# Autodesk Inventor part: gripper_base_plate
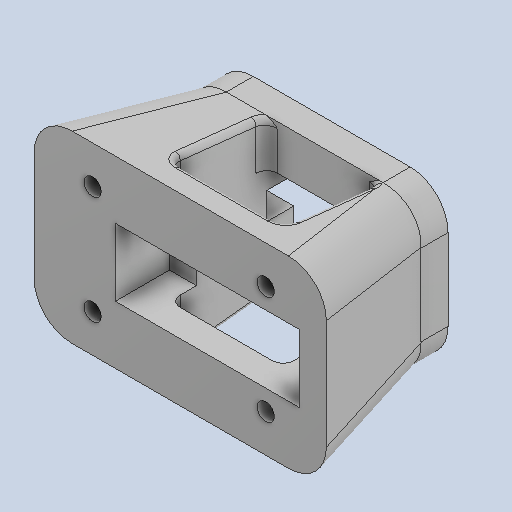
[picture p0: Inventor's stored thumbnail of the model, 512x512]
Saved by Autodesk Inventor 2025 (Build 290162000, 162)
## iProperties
Created: 2025-06
Part Number: gripper_base_plate
Material: Plastica ABS
Document SubType Name: Modeling
Designer: Ryzen5700u
Density: 1.06 g/cm^3
Appearance: Default
Author: Ryzen5700u
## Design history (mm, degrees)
feature "Solido1"
node "Solido2"
